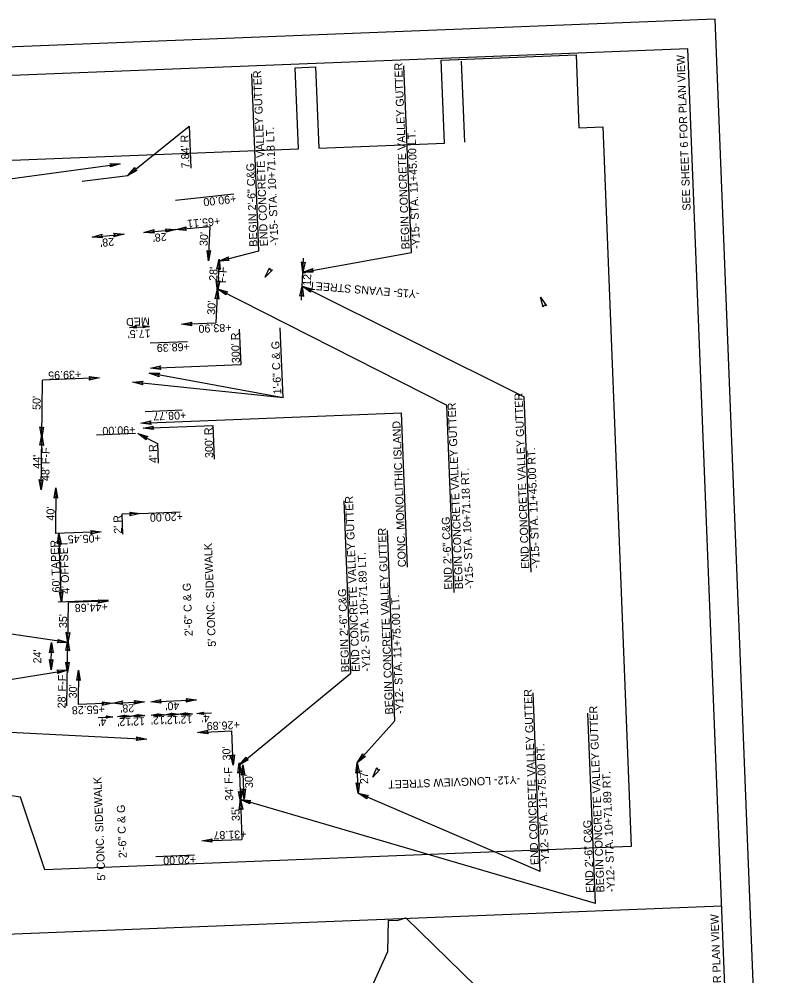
# Model space of a CAD drawing. Extents: x 1627811 to 1628977, y 762656 to 764629.
# Drawn here: x 1628301 to 1628977, y 763561 to 764398 of the extents above; entities that cross this region are included whole.
import ezdxf

# ---------------------------------------------------------------- set-up
doc = ezdxf.new("R2010")
doc.units = 0
for name, color, linetype in [('Default', 7, 'Continuous'), ('Prop Dimension', 7, 'Continuous'), ('Prop Dimension Text', 7, 'Continuous'), ('Prop DSN Text', 7, 'Continuous'), ('Prop Terminator CELL', 7, 'Continuous'), ('Sheet Clip Boundary CELL', 7, 'Continuous'), ('Sheet Plan And Profile CELL', 7, 'Continuous'), ('Sheet Plot Border Outside CELL', 7, 'Continuous')]:
    doc.layers.add(name, color=color, linetype=linetype)

msp = doc.modelspace()

# ---------------------------------------------------------------- linework, layer by layer
at = {"layer": 'Prop Dimension'}
for p, q in [((1628690.69, 764290.33), (1628687.9, 764361.22)), ((1628643.9, 764193.91), (1628637.46, 764357.3)), ((1628510.65, 764195.54), (1628504.56, 764350.03)), ((1628395.93, 764261.34), (1628449.7, 764304.26)), ((1628449.7, 764304.26), (1628451.14, 764267.59)), ((1628258.89, 764253.65), (1628389.33, 764271.55)), ((1628356.04, 764256.29), (1628395.93, 764261.34)), ((1628437.73, 764239.69), (1628488.66, 764245.17)), ((1628364.79, 764207.49), (1628392.67, 764209.98)), ((1628410.11, 764211.53), (1628437.99, 764214.02)), ((1628437.99, 764214.02), (1628467.88, 764216.68)), ((1628466.4, 764186.72), (1628467.88, 764216.68)), ((1628475.62, 764186.27), (1628510.65, 764195.54)), ((1628549.05, 764176.66), (1628643.9, 764193.91)), ((1628475.72, 764188.26), (1628474.34, 764160.3)), ((1628549.05, 764176.66), (1628549.65, 764188.9)), ((1628548.17, 764158.67), (1628549.35, 764182.64)), ((1628474.44, 764162.3), (1628472.97, 764132.33)), ((1628474.44, 764162.3), (1628674.82, 764060.36)), ((1628547.86, 764152.4), (1628548.46, 764164.64)), ((1628548.46, 764164.64), (1628742.6, 764067.62)), ((1628397.56, 764128.49), (1628415.05, 764129.18)), ((1628442.99, 764131.15), (1628472.97, 764132.33)), ((1628493.46, 764126.82), (1628494.68, 764096.04)), ((1628531.69, 764066.99), (1628529.29, 764127.99)), ((1628448.03, 764115.82), (1628415.62, 764114.54)), ((1628415.7, 764092.93), (1628494.68, 764096.04)), ((1628371.28, 764084.33), (1628321.32, 764082.36)), ((1628531.69, 764066.99), (1628414.76, 764088.44)), ((1628320.67, 764032.36), (1628321.32, 764082.36)), ((1628531.69, 764066.99), (1628400.19, 764080.71)), ((1628748.64, 763914.59), (1628742.6, 764067.62)), ((1628681.28, 763896.58), (1628674.82, 764060.36)), ((1628407.23, 764044.7), (1628635.33, 764053.69)), ((1628443.64, 764055.98), (1628411.23, 764054.7)), ((1628640.66, 763918.72), (1628635.33, 764053.69)), ((1628409.29, 764040.3), (1628470.36, 764042.71)), ((1628470.36, 764042.71), (1628471.53, 764013.18)), ((1628320.07, 763986.37), (1628320.69, 764034.36)), ((1628402.66, 764035.58), (1628368.47, 764034.23)), ((1628404.72, 764035.7), (1628421.83, 764027)), ((1628421.83, 764027), (1628422.51, 764009.86)), ((1628333.13, 763988.2), (1628332.61, 763948.2)), ((1628591, 763826.04), (1628585.06, 763976.85)), ((1628406.73, 763965.69), (1628441.7, 763967.07)), ((1628406.73, 763965.69), (1628390.74, 763965.06)), ((1628390.74, 763965.06), (1628391.42, 763947.77)), ((1628372.58, 763949.78), (1628332.61, 763948.2)), ((1628629.49, 763784.39), (1628622.92, 763951)), ((1628338.1, 763888.37), (1628335.73, 763948.32)), ((1628378.94, 763889.98), (1628334.98, 763888.25)), ((1628343.52, 763852.84), (1628344, 763887.84)), ((1628378.97, 763889.21), (1628344, 763887.84)), ((1628343.52, 763852.84), (1628186.47, 763876.05)), ((1628328.84, 763829.05), (1628329.18, 763853.04)), ((1628342.73, 763797.69), (1628343.54, 763854.84)), ((1628150.43, 763797.78), (1628343.17, 763828.84)), ((1628352.95, 763828.7), (1628352.56, 763798.7)), ((1628493.4, 763745.81), (1628591, 763826.04)), ((1628756.61, 763652.7), (1628750.45, 763808.96)), ((1628382.5, 763799.89), (1628352.52, 763798.7)), ((1628382.5, 763799.89), (1628410.47, 763800.99)), ((1628415.97, 763801.21), (1628455.94, 763802.78)), ((1628440.42, 763790.26), (1628452.41, 763790.73)), ((1628456.41, 763790.89), (1628469.28, 763791.4)), ((1628804.92, 763624.66), (1628798.35, 763791.27)), ((1628369.97, 763787.48), (1628382.96, 763787.99)), ((1628386.96, 763788.15), (1628398.95, 763788.63)), ((1628398.95, 763788.63), (1628410.94, 763789.1)), ((1628416.44, 763789.31), (1628428.43, 763789.79)), ((1628428.43, 763789.79), (1628440.42, 763790.26)), ((1628629.49, 763784.39), (1628596.5, 763747.78)), ((1628171.66, 763780.6), (1628412.51, 763768.42)), ((1628457.06, 763774.41), (1628487.03, 763775.59)), ((1628488.13, 763745.61), (1628487.03, 763775.59)), ((1628493.32, 763747.81), (1628494.57, 763713.83)), ((1628497.6, 763715.94), (1628496.5, 763745.92)), ((1628597.47, 763721.3), (1628596.5, 763747.78)), ((1628494.49, 763715.83), (1628495.77, 763680.85)), ((1628804.92, 763624.66), (1628494.49, 763715.83)), ((1628756.61, 763652.7), (1628597.47, 763721.3)), ((1628460.8, 763679.47), (1628495.77, 763680.85)), ((1628420.55, 763666), (1628454.41, 763667.34)), ((1627866.03, 763581.23), (1628915.21, 763622.6))]:
    msp.add_line(p, q, dxfattribs=at)
at = {"layer": 'Prop Terminator CELL'}
for points in [[(1628380.2, 764271.86), (1628389.33, 764271.55), (1628380.58, 764268.74), (1628381.5, 764270.48)], [(1628403.93, 764265.75), (1628395.93, 764261.34), (1628402, 764268.24), (1628402.1, 764266.27)], [(1628373.89, 764206.74), (1628364.79, 764207.49), (1628373.66, 764209.89), (1628372.65, 764208.19)], [(1628383.57, 764210.72), (1628392.67, 764209.98), (1628383.8, 764207.58), (1628384.81, 764209.27)], [(1628419.21, 764210.79), (1628410.11, 764211.53), (1628418.98, 764213.93), (1628417.97, 764212.23)], [(1628428.89, 764214.76), (1628437.99, 764214.02), (1628429.12, 764211.62), (1628430.13, 764213.32)], [(1628447.1, 764213.27), (1628437.99, 764214.02), (1628446.87, 764216.41), (1628445.86, 764214.72)], [(1628468.39, 764195.63), (1628466.4, 764186.72), (1628465.25, 764195.83), (1628466.79, 764194.61)], [(1628473.73, 764179.35), (1628475.72, 764188.26), (1628476.87, 764179.15), (1628475.33, 764180.37)], [(1628484.72, 764187.07), (1628475.62, 764186.27), (1628483.96, 764190.13), (1628483.26, 764188.29)], [(1628551.04, 764185.58), (1628549.05, 764176.66), (1628547.9, 764185.78), (1628549.44, 764184.55)], [(1628522.47, 764178.66), (1628515.94, 764172.27), (1628519.94, 764180.54), (1628520.57, 764178.67)], [(1628558.18, 764176.75), (1628549.05, 764176.66), (1628557.67, 764179.86), (1628556.82, 764178.08)], [(1628476.33, 764169.21), (1628474.34, 764160.3), (1628473.19, 764169.42), (1628474.73, 764168.19)], [(1628472.45, 764153.38), (1628474.44, 764162.3), (1628475.59, 764153.18), (1628474.05, 764154.4)], [(1628481.76, 764156.83), (1628474.44, 764162.3), (1628483.23, 764159.62), (1628481.48, 764158.71)], [(1628546.47, 764155.73), (1628548.46, 764164.64), (1628549.61, 764155.52), (1628548.07, 764156.75)], [(1628555.82, 764159.23), (1628548.46, 764164.64), (1628557.27, 764162.02), (1628555.53, 764161.11)], [(1628759.28, 764146.12), (1628756.71, 764154.89), (1628762.13, 764147.46), (1628760.18, 764147.79)], [(1628403.44, 764127.66), (1628397.56, 764128.49), (1628403.41, 764129.7), (1628402.69, 764128.64)], [(1628409.17, 764130.01), (1628415.05, 764129.18), (1628409.2, 764127.96), (1628409.91, 764129.02)], [(1628452.04, 764129.96), (1628442.99, 764131.15), (1628451.97, 764133.1), (1628450.88, 764131.46)], [(1628424.75, 764091.74), (1628415.7, 764092.93), (1628424.68, 764094.89), (1628423.59, 764093.24)], [(1628362.23, 764085.52), (1628371.28, 764084.33), (1628362.3, 764082.37), (1628363.39, 764084.02)], [(1628423.34, 764085.29), (1628414.76, 764088.44), (1628423.96, 764088.38), (1628422.54, 764087.01)], [(1628408.98, 764078.24), (1628400.19, 764080.71), (1628409.36, 764081.37), (1628408.05, 764079.89)], [(1628322.34, 764041.34), (1628320.67, 764032.36), (1628319.19, 764041.43), (1628320.77, 764040.26)], [(1628416.29, 764043.5), (1628407.23, 764044.7), (1628416.21, 764046.65), (1628415.13, 764045.01)], [(1628418.34, 764039.1), (1628409.29, 764040.3), (1628418.27, 764042.25), (1628417.18, 764040.61)], [(1628319.03, 764025.38), (1628320.69, 764034.36), (1628322.18, 764025.29), (1628320.59, 764026.46)], [(1628412.04, 764030.24), (1628404.72, 764035.7), (1628413.51, 764033.02), (1628411.76, 764032.12)], [(1628321.74, 763995.35), (1628320.07, 763986.37), (1628318.59, 763995.44), (1628320.17, 763994.27)], [(1628331.47, 763979.22), (1628333.13, 763988.2), (1628334.61, 763979.13), (1628333.03, 763980.3)], [(1628397.68, 763966.88), (1628406.73, 763965.69), (1628397.75, 763963.73), (1628398.84, 763965.38)], [(1628363.53, 763950.97), (1628372.58, 763949.78), (1628363.6, 763947.82), (1628364.69, 763949.47)], [(1628334.54, 763939.27), (1628335.73, 763948.32), (1628337.69, 763939.34), (1628336.04, 763940.43)], [(1628339.29, 763897.42), (1628338.1, 763888.37), (1628336.14, 763897.35), (1628337.78, 763896.26)], [(1628369.92, 763890.41), (1628378.97, 763889.21), (1628369.99, 763887.26), (1628371.08, 763888.9)], [(1628345.19, 763861.82), (1628343.52, 763852.84), (1628342.04, 763861.91), (1628343.62, 763860.74)], [(1628327.5, 763844.06), (1628329.18, 763853.04), (1628330.65, 763843.97), (1628329.06, 763845.14)], [(1628334.84, 763855.69), (1628343.52, 763852.84), (1628334.33, 763852.58), (1628335.7, 763853.99)], [(1628341.87, 763845.86), (1628343.54, 763854.84), (1628345.01, 763845.77), (1628343.43, 763846.94)], [(1628330.51, 763838.03), (1628328.84, 763829.05), (1628327.36, 763838.12), (1628328.95, 763836.95)], [(1628344.82, 763835.82), (1628343.15, 763826.84), (1628341.67, 763835.91), (1628343.26, 763834.74)], [(1628334.04, 763828.94), (1628343.17, 763828.84), (1628334.49, 763825.82), (1628335.37, 763827.58)], [(1628351.29, 763819.72), (1628352.95, 763828.7), (1628354.43, 763819.63), (1628352.85, 763820.8)], [(1628373.44, 763801.08), (1628382.5, 763799.89), (1628373.52, 763797.93), (1628374.6, 763799.57)], [(1628391.55, 763798.69), (1628382.5, 763799.89), (1628391.48, 763801.84), (1628390.39, 763800.2)], [(1628401.42, 763802.18), (1628410.47, 763800.99), (1628401.49, 763799.03), (1628402.58, 763800.68)], [(1628425.02, 763800.01), (1628415.97, 763801.21), (1628424.95, 763803.16), (1628423.86, 763801.52)], [(1628446.88, 763803.98), (1628455.94, 763802.78), (1628446.96, 763800.83), (1628448.04, 763802.47)], [(1628422.32, 763788.54), (1628416.44, 763789.31), (1628422.28, 763790.59), (1628421.57, 763789.52)], [(1628422.54, 763790.56), (1628428.43, 763789.79), (1628422.59, 763788.52), (1628423.3, 763789.59)], [(1628434.31, 763789.01), (1628428.43, 763789.79), (1628434.27, 763791.06), (1628433.56, 763789.99)], [(1628434.53, 763791.04), (1628440.42, 763790.26), (1628434.58, 763788.99), (1628435.29, 763790.06)], [(1628446.31, 763789.48), (1628440.42, 763790.26), (1628446.26, 763791.53), (1628445.55, 763790.46)], [(1628446.53, 763791.51), (1628452.41, 763790.73), (1628446.57, 763789.46), (1628447.28, 763790.53)], [(1628462.29, 763790.11), (1628456.41, 763790.89), (1628462.24, 763792.16), (1628461.54, 763791.09)], [(1628377.08, 763788.77), (1628382.96, 763787.99), (1628377.13, 763786.72), (1628377.83, 763787.79)], [(1628392.85, 763787.38), (1628386.96, 763788.15), (1628392.8, 763789.42), (1628392.09, 763788.35)], [(1628393.07, 763789.4), (1628398.95, 763788.63), (1628393.12, 763787.35), (1628393.82, 763788.42)], [(1628404.84, 763787.85), (1628398.95, 763788.63), (1628404.79, 763789.9), (1628404.08, 763788.83)], [(1628405.06, 763789.87), (1628410.94, 763789.1), (1628405.11, 763787.83), (1628405.81, 763788.9)], [(1628466.11, 763773.22), (1628457.06, 763774.41), (1628466.04, 763776.37), (1628464.95, 763774.72)], [(1628403.6, 763770.43), (1628412.51, 763768.42), (1628403.39, 763767.28), (1628404.62, 763768.82)], [(1628489.35, 763754.67), (1628488.13, 763745.61), (1628486.2, 763754.6), (1628487.84, 763753.51)], [(1628501.33, 763750.33), (1628493.4, 763745.81), (1628499.37, 763752.79), (1628499.5, 763750.82)], [(1628603.68, 763753.43), (1628596.5, 763747.78), (1628601.37, 763755.57), (1628601.79, 763753.65)], [(1628492.1, 763738.76), (1628493.32, 763747.81), (1628495.25, 763738.82), (1628493.61, 763739.91)], [(1628495.28, 763736.87), (1628496.5, 763745.92), (1628498.43, 763736.94), (1628496.79, 763738.03)], [(1628595.28, 763738.73), (1628596.5, 763747.78), (1628598.43, 763738.79), (1628596.79, 763739.88)], [(1628616.43, 763741.86), (1628610.32, 763735.08), (1628613.8, 763743.59), (1628614.54, 763741.76)], [(1628498.82, 763724.99), (1628497.6, 763715.94), (1628495.67, 763724.93), (1628497.31, 763723.84)], [(1628598.69, 763730.35), (1628597.47, 763721.3), (1628595.54, 763730.28), (1628597.18, 763729.19)], [(1628495.79, 763722.88), (1628494.57, 763713.83), (1628492.64, 763722.81), (1628494.28, 763721.72)], [(1628493.27, 763706.78), (1628494.49, 763715.83), (1628496.42, 763706.84), (1628494.78, 763707.93)], [(1628502.69, 763711.8), (1628494.49, 763715.83), (1628503.63, 763714.81), (1628502.07, 763713.6)], [(1628605.12, 763716.31), (1628597.47, 763721.3), (1628606.42, 763719.18), (1628604.73, 763718.17)], [(1628469.86, 763678.28), (1628460.8, 763679.47), (1628469.78, 763681.43), (1628468.7, 763679.78)]]:
    msp.add_lwpolyline(points, close=True, dxfattribs=at)
at = {"layer": 'Sheet Clip Boundary CELL'}
for points in [[(1628323.41, 763654.34), (1628302.22, 763717.7), (1628208.23, 763732.1), (1628213.32, 763650), (1628196.97, 763631.82), (1628183.33, 763633.23), (1628068.1, 763644.27), (1628043.63, 764264.81), (1628156.85, 764269.28), (1628154, 764341.74), (1628173.63, 764342.52), (1628176.48, 764270.05), (1628545.1, 764284.59), (1628542.3, 764355.48), (1628560.15, 764356.18), (1628562.95, 764285.29), (1628672.78, 764289.62), (1628669.92, 764362.09), (1628787.91, 764366.75), (1628790.42, 764303.08), (1628811.34, 764303.9), (1628836.16, 763674.56)], [(1628080.25, 762943.5), (1628060.66, 763440.11), (1628567.89, 763460.11), (1628623.39, 763582.83), (1628623.86, 763610.17), (1628631.44, 763609.98), (1628639.19, 763612.32), (1628786.08, 763468.72), (1628805.66, 762972.11)]]:
    msp.add_lwpolyline(points, close=True, dxfattribs=at)
at = {"layer": 'Sheet Plan And Profile CELL'}
msp.add_lwpolyline([(1627836.47, 764330.65), (1627895.58, 762831.81), (1628944.76, 762873.18), (1628885.66, 764372.02)], close=True, dxfattribs=at)
at = {"layer": 'Sheet Plot Border Outside CELL'}
msp.add_lwpolyline([(1628976.64, 762699.3), (1628909.65, 764397.98), (1627810.51, 764354.64), (1627877.49, 762655.96)], close=True, dxfattribs=at)

# ---------------------------------------------------------------- texts
at = {"layer": 'Default'}
for s, p in [('SEE SHEET 6 FOR PLAN VIEW', (1628888.14, 764230.67)), ('SEE SHEET 5 FOR PLAN VIEW', (1628917.76, 763479.38))]:
    msp.add_text(s, height=7, rotation=92.25819, dxfattribs=at).set_placement(p)
at = {"layer": 'Prop Dimension'}
for s, p in [('+68.39', (1628450.05, 764115.02)), ('+08.77', (1628446.94, 764055.21)), ('+90.00', (1628402.48, 764042.43)), ('+20.00', (1628444, 763966.61)), ('+20.00', (1628455.64, 763666.79))]:
    msp.add_text(s, height=7, rotation=182.25819, dxfattribs=at).set_placement(p)
at = {"layer": 'Prop Dimension Text'}
for s, rotation, p in [('BEGIN CONCRETE VALLEY GUTTER', 92.25819, (1628642.35, 764196.84)), ('END CONCRETE VALLEY GUTTER', 92.25819, (1628518.55, 764199.46)), ('-Y15- STA. 10+71.18 LT.', 92.25819, (1628527.72, 764199.82)), ("7.84' R", 92.05859, (1628450.01, 764267.66)), ('-Y15- STA. 11+45.00 LT.', 92.25819, (1628651.52, 764197.2)), ('BEGIN 2\'-6" C&G', 92.25819, (1628509.38, 764199.1)), ('+90.00', 186.1376, (1628490.46, 764244.41)), ('+65.11', 185.09122, (1628476.47, 764224.94)), ("28'", 185.09676, (1628429.64, 764211.18)), ("30'", 86.61163, (1628465.61, 764199.45)), ("28'", 185.09676, (1628383.7, 764206.86)), ("28'", 86.61163, (1628473.96, 764168.96)), ('F-F', 86.61163, (1628481.89, 764166.95)), ("12'", 86.61163, (1628555.85, 764164.56)), ("30'", 86.61163, (1628472.26, 764139.38)), ('MED', 182.25819, (1628415.07, 764137.43)), ("17.5'", 182.25819, (1628415.67, 764126.72)), ('+83.90', 182.25819, (1628486.53, 764131.81)), ("300' R", 92.05859, (1628494.05, 764097.35)), ('+39.95', 182.25819, (1628355.08, 764090.95)), ("50'", 89.25608, (1628319.63, 764056.28)), ('END CONCRETE VALLEY GUTTER', 92.25819, (1628747.08, 763917.51)), ('BEGIN CONCRETE VALLEY GUTTER', 92.25819, (1628689.06, 763899.66)), ("300' R", 92.05859, (1628470.73, 764014.39)), ("4' R", 92.05859, (1628421.82, 764010.06)), ("44'", 89.25608, (1628319.93, 764004.84)), ("48' F-F", 89.25608, (1628327.36, 763994.08)), ('-Y15- STA. 11+45.00 RT.', 92.25819, (1628756.25, 763917.87)), ('-Y15- STA. 10+71.18 RT.', 92.25819, (1628698.23, 763900.02)), ('END CONCRETE VALLEY GUTTER', 92.25819, (1628598.86, 763827.42)), ("40'", 89.25608, (1628331.82, 763959.5)), ("2' R", 92.05859, (1628390.89, 763948.24)), ('END 2\'-6" C&G', 92.25819, (1628679.89, 763899.3)), ('BEGIN CONCRETE VALLEY GUTTER', 92.25819, (1628628.09, 763790.21)), ("60' TAPER", 92.25819, (1628337.04, 763896.82)), ("4' OFFSET", 92.25819, (1628345.05, 763895.65)), ('+05.45', 182.25819, (1628372.18, 763947.7)), ('-Y12- STA. 10+71.89 LT.', 92.25819, (1628608.03, 763827.79)), ('BEGIN 2\'-6" C&G', 92.25819, (1628589.69, 763827.06)), ('-Y12- STA. 11+75.00 LT.', 92.25819, (1628637.26, 763790.58)), ('+44.68', 182.25819, (1628378.32, 763887.59)), ("35'", 89.14069, (1628342.8, 763865.54)), ("24'", 89.12268, (1628320.26, 763834.61)), ("28' F-F", 89.12268, (1628341.57, 763795.33)), ("30'", 89.10794, (1628351.35, 763804.09)), ('END CONCRETE VALLEY GUTTER', 92.25819, (1628755.22, 763658.52)), ("28'", 182.25819, (1628401.48, 763799.07)), ("40'", 182.25819, (1628440.9, 763801.08)), ('+55.28', 182.25819, (1628375.74, 763798.14)), ('BEGIN CONCRETE VALLEY GUTTER', 92.25819, (1628812.8, 763634.55)), ("4'", 182.25819, (1628377.07, 763787.04)), ("12'", 182.25819, (1628398.86, 763787.21)), ("12'", 182.25819, (1628410.85, 763787.68)), ("12'", 182.25819, (1628428.2, 763788.65)), ("12'", 182.25819, (1628440.33, 763788.84)), ("12'", 182.25819, (1628452.32, 763789.31)), ("4'", 182.25819, (1628467.28, 763790.36)), ('+26.89', 182.25819, (1628493.7, 763784.43)), ("30'", 92.05859, (1628485.98, 763749.96)), ('-Y12- STA. 11+75.00 RT.', 92.25819, (1628764.38, 763658.89)), ("34' F-F", 92.05859, (1628488.2, 763714.7)), ("27'", 92.05859, (1628606.2, 763729.37)), ("30'", 92.05859, (1628505.54, 763725.79)), ('-Y12- STA. 10+71.89 RT.', 92.25819, (1628821.97, 763634.92)), ("35'", 92.05859, (1628493.98, 763697.01)), ('END 2\'-6" C&G', 92.25819, (1628803.63, 763634.19)), ('+31.87', 182.25819, (1628499.58, 763688.87))]:
    msp.add_text(s, height=7, rotation=rotation, dxfattribs=at).set_placement(p)
at = {"layer": 'Prop DSN Text'}
for s, rotation, p in [('-Y15- EVANS STREET', 175.44778, (1628651.29, 764160.85)), ('1\'-6" C & G', 92.25819, (1628530.23, 764070.05)), ('CONC. MONOLITHIC ISLAND', 92.25819, (1628639.28, 763918.97)), ("5' CONC. SIDEWALK", 92.25819, (1628473.07, 763849.38)), ('2\'-6" C & G', 92.25819, (1628452.73, 763858.61)), ("5' CONC. SIDEWALK", 92.25819, (1628376.37, 763644.91)), ('-Y12- LONGVIEW STREET', 182.09642, (1628738.96, 763736.44)), ('2\'-6" C & G', 92.25819, (1628395.14, 763664.59))]:
    msp.add_text(s, height=7, rotation=rotation, dxfattribs=at).set_placement(p)

doc.saveas('drawing.dxf')
